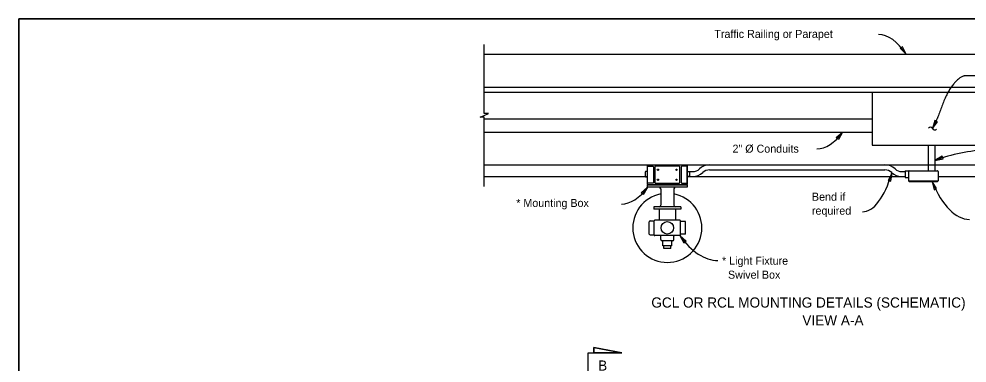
# Model space of a CAD drawing. Extents: x 0 to 20.5, y 0 to 13.
# Drawn here: x 0 to 11.94, y 8.64 to 12.97 of the extents above; entities that cross this region are included whole.
import ezdxf

# ---------------------------------------------------------------- set-up
doc = ezdxf.new("R2010")
doc.units = 0
for name, color, linetype in [('ActivePts-ConstElements', 7, 'Continuous'), ('Dimension', 7, 'Continuous'), ('Miscellaneous1', 7, 'Continuous'), ('NavLight', 7, 'Continuous'), ('NavLight_h', 7, 'Continuous'), ('SupstrConc', 7, 'Continuous'), ('SupstrConc_h', 7, 'Continuous'), ('TextStructures', 7, 'Continuous')]:
    doc.layers.add(name, color=color, linetype=linetype)

msp = doc.modelspace()

# ---------------------------------------------------------------- linework, layer by layer
at = {"layer": 'ActivePts-ConstElements'}
msp.add_lwpolyline([(0, 0), (20.525, 0), (20.525, 12.973), (0, 12.973)], close=True, dxfattribs=at)
at = {"layer": 'Dimension'}
for p, q in [((7.59, 8.767), (7.239, 8.837)), ((7.239, 8.837), (7.239, 8.767)), ((7.168, 8.486), (7.168, 8.767)), ((7.168, 8.767), (7.59, 8.767))]:
    msp.add_line(p, q, dxfattribs=at)
msp.add_lwpolyline([(5.858, 10.862), (5.858, 11.737), (5.806, 11.737), (5.858, 11.759), (5.91, 11.782), (5.858, 11.782), (5.858, 12.65)], dxfattribs=at)
for points in [[(11.17, 12.53), (11.123, 12.624), (11.094, 12.604)], [(11.502, 11.592), (11.565, 11.677), (11.533, 11.693)], [(10.37, 11.549), (10.317, 11.457), (10.29, 11.48)], [(11.532, 11.189), (11.636, 11.21), (11.623, 11.243)], [(10.992, 11.035), (10.945, 10.94), (10.978, 10.93)], [(11.498, 10.926), (11.521, 10.823), (11.554, 10.836)], [(7.913, 10.854), (7.861, 10.762), (7.833, 10.785)], [(8.322, 10.246), (8.371, 10.152), (8.399, 10.173)], [(7.239, 8.767), (7.239, 8.837), (7.59, 8.767)]]:
    msp.add_lwpolyline(points, close=True, dxfattribs=at)
for centre, radius, start, end in [((11.475, 11.579), 0.0298, 25.4334, 137.1606), ((11.529, 11.605), 0.0298, 205.4334, 317.1606), ((12.259, 9.286), 2.038, 91.7582, 110.8927)]:
    msp.add_arc(centre, radius, start, end, dxfattribs=at)
for centre, major_axis, ratio, start_param, end_param in [((10.803, 10.939), (-0.017, -1.837), 0.385201, 2.621299, 3.14161), ((10.027, 13.173), (0.017, -1.837), 0.385201, 0.000035, 0.481977), ((10.606, 12.172), (-0.014, 1.628), 0.323643, 3.141636, 3.936281), ((11.984, 12.285), (-0.017, -1.837), 0.385201, 5.549281, 6.283151), ((7.57, 12.479), (0.017, -1.837), 0.385201, 0.000035, 0.481977), ((8.784, 12.201), (-0.016, 2.269), 0.411716, 2.607161, 3.141582)]:
    msp.add_ellipse(centre, major_axis=major_axis, ratio=ratio, start_param=start_param, end_param=end_param, dxfattribs=at)
msp.add_open_spline([(12.06, 12.255), (11.963, 12.255), (11.853, 12.255), (11.689, 12.064), (11.56, 11.705), (11.502, 11.592)], degree=2, dxfattribs=at)
at = {"layer": 'Miscellaneous1'}
msp.add_lwpolyline([(0, 12.973), (20.525, 12.973), (20.525, 0), (0, 0)], close=True, dxfattribs=at)
at = {"layer": 'NavLight'}
for p, q in [((11.449, 11.134), (11.532, 11.134)), ((11.449, 11.134), (11.449, 11.061)), ((11.532, 11.134), (11.532, 11.061)), ((8.439, 11.051), (8.483, 11.051)), ((8.439, 10.988), (8.483, 10.988)), ((8.695, 11.072), (10.903, 11.072)), ((11.115, 11.051), (11.159, 11.051)), ((11.117, 10.988), (11.159, 10.988)), ((11.159, 11.061), (11.563, 11.061)), ((11.159, 11.061), (11.159, 10.978)), ((11.2, 11.051), (11.2, 10.936)), ((11.573, 11.051), (11.573, 10.936)), ((11.159, 10.978), (11.2, 10.978)), ((11.2, 10.936), (11.573, 10.936)), ((11.21, 10.926), (11.563, 10.926)), ((8.08, 10.833), (8.08, 10.626)), ((8.246, 10.833), (8.246, 10.626)), ((8.332, 10.606), (7.995, 10.606)), ((7.995, 10.606), (7.995, 10.579)), ((8.332, 10.579), (7.995, 10.579)), ((8.062, 10.579), (8.062, 10.439)), ((8.264, 10.579), (8.264, 10.439)), ((8.332, 10.606), (8.332, 10.579)), ((7.934, 10.264), (7.934, 10.42)), ((7.945, 10.431), (7.996, 10.431)), ((7.996, 10.254), (7.996, 10.43)), ((8.322, 10.439), (8.004, 10.439)), ((8.33, 10.254), (8.33, 10.43)), ((8.39, 10.422), (8.33, 10.422)), ((8.392, 10.265), (8.392, 10.42)), ((7.945, 10.254), (7.996, 10.254)), ((8.073, 10.246), (8.004, 10.246)), ((8.253, 10.246), (8.073, 10.246)), ((8.082, 10.195), (8.082, 10.237)), ((8.228, 10.179), (8.098, 10.179)), ((8.105, 10.115), (8.105, 10.179)), ((8.221, 10.115), (8.221, 10.179)), ((8.244, 10.195), (8.244, 10.237)), ((8.322, 10.246), (8.253, 10.246)), ((8.39, 10.263), (8.33, 10.263)), ((8.221, 10.115), (8.105, 10.115)), ((8.12, 10.083), (8.12, 10.115)), ((8.206, 10.083), (8.12, 10.083)), ((8.131, 10.083), (8.131, 10.083)), ((8.206, 10.083), (8.206, 10.115))]:
    msp.add_line(p, q, dxfattribs=at)
for points in [[(8.406, 10.884), (7.92, 10.884), (7.913, 10.892), (7.913, 11.127), (7.92, 11.134), (8.406, 11.134), (8.413, 11.127), (8.413, 10.892)], [(7.913, 11.12), (7.98, 11.12), (7.987, 11.112), (7.987, 10.91), (7.98, 10.903), (7.913, 10.903)], [(8.314, 11.12), (8.01, 11.12), (8.004, 11.112), (8.004, 10.91), (8.01, 10.903), (8.314, 10.903), (8.32, 10.91), (8.32, 11.112)], [(8.413, 11.12), (8.345, 11.12), (8.339, 11.112), (8.339, 10.91), (8.345, 10.903), (8.413, 10.903)], [(7.912, 11.05), (7.888, 11.05), (7.883, 11.045), (7.883, 10.99), (7.888, 10.984), (7.912, 10.984)], [(8.413, 11.052), (8.438, 11.052), (8.443, 11.047), (8.443, 10.992), (8.438, 10.987), (8.413, 10.987)], [(8.413, 10.884), (8.413, 10.854), (7.913, 10.854), (7.913, 10.884)]]:
    msp.add_lwpolyline(points, close=True, dxfattribs=at)
for centre, radius in [((8.045, 11.074), 0.00794), ((8.279, 11.074), 0.00794), ((8.045, 10.948), 0.00794), ((8.279, 10.948), 0.00794), ((8.163, 10.342), 0.0792)]:
    msp.add_circle(centre, radius, dxfattribs=at)
for centre, radius, start, end in [((8.695, 10.947), 0.188, 90, 132.8379), ((10.903, 10.947), 0.188, 47.1621, 90), ((8.483, 11.176), 0.125, 270.0051, 312.8379), ((8.483, 11.176), 0.188, 270.0041, 312.8379), ((8.695, 10.947), 0.125, 90, 132.8379), ((10.903, 10.947), 0.125, 47.1621, 90), ((11.115, 11.176), 0.188, 227.1621, 270), ((11.115, 11.176), 0.125, 227.1621, 270), ((11.21, 11.051), 0.0104, 90, 180), ((11.563, 11.051), 0.0104, 0, 90), ((11.21, 10.936), 0.0104, 180, 270), ((11.563, 10.936), 0.0104, 270, 0), ((8.163, 10.342), 0.435, 101.0398, 78.9588), ((8.059, 10.833), 0.0208, 0.0196, 90), ((8.267, 10.833), 0.0208, 90, 180), ((8.059, 10.626), 0.0208, 270, 0), ((8.267, 10.626), 0.0208, 180, 270), ((7.945, 10.42), 0.0104, 90, 179.9777), ((8.004, 10.43), 0.00854, 90, 180), ((8.322, 10.43), 0.00854, 0, 90), ((8.39, 10.42), 0.00201, 0, 90), ((7.945, 10.264), 0.0104, 180, 270), ((8.004, 10.254), 0.00854, 180, 270), ((8.073, 10.237), 0.00854, 0, 90), ((8.098, 10.195), 0.0156, 180, 270), ((8.228, 10.195), 0.0156, 270, 360), ((8.252, 10.237), 0.00854, 90, 180), ((8.322, 10.254), 0.00854, 270, 0), ((8.39, 10.265), 0.00201, 270, 0)]:
    msp.add_arc(centre, radius, start, end, dxfattribs=at)
at = {"layer": 'NavLight_h'}
for p, q in [((5.858, 11.716), (10.741, 11.716)), ((5.858, 11.549), (10.741, 11.549)), ((11.449, 11.382), (11.449, 11.134)), ((11.532, 11.382), (11.532, 11.134))]:
    msp.add_line(p, q, dxfattribs=at)
at = {"layer": 'SupstrConc'}
for p, q in [((5.858, 12.53), (13.924, 12.53)), ((5.858, 12.113), (13.924, 12.113)), ((5.858, 12.049), (13.924, 12.049)), ((5.858, 11.134), (13.924, 11.134)), ((5.858, 10.988), (7.913, 10.988)), ((8.413, 10.988), (11.159, 10.988)), ((11.573, 10.988), (13.39, 10.988))]:
    msp.add_line(p, q, dxfattribs=at)
at = {"layer": 'SupstrConc_h'}
for p, q in [((10.741, 12.049), (10.741, 11.382)), ((10.741, 11.382), (12.241, 11.382))]:
    msp.add_line(p, q, dxfattribs=at)

# ---------------------------------------------------------------- texts
at = {"layer": 'Dimension'}
for s, height, p in [('Bend if', 0.1008, (9.984, 10.684)), ('required', 0.1008, (9.984, 10.508)), ('* Light Fixture', 0.1008, (8.852, 9.878)), ('  Swivel Box', 0.1008, (8.852, 9.702)), ('GCL OR RCL MOUNTING DETAILS (SCHEMATIC)', 0.128, (7.962, 9.338)), ('VIEW A-A', 0.128, (9.863, 9.114))]:
    msp.add_text(s, height=height, dxfattribs=at).set_placement(p)
at = {"layer": 'TextStructures'}
for s, height, p in [('Traffic Railing or Parapet', 0.1008, (8.755, 12.734)), ('2" Ø Conduits', 0.1008, (8.984, 11.289)), ('* Mounting Box', 0.1008, (6.261, 10.605)), ('B', 0.128, (7.292, 8.544))]:
    msp.add_text(s, height=height, dxfattribs=at).set_placement(p)

doc.saveas('drawing.dxf')
